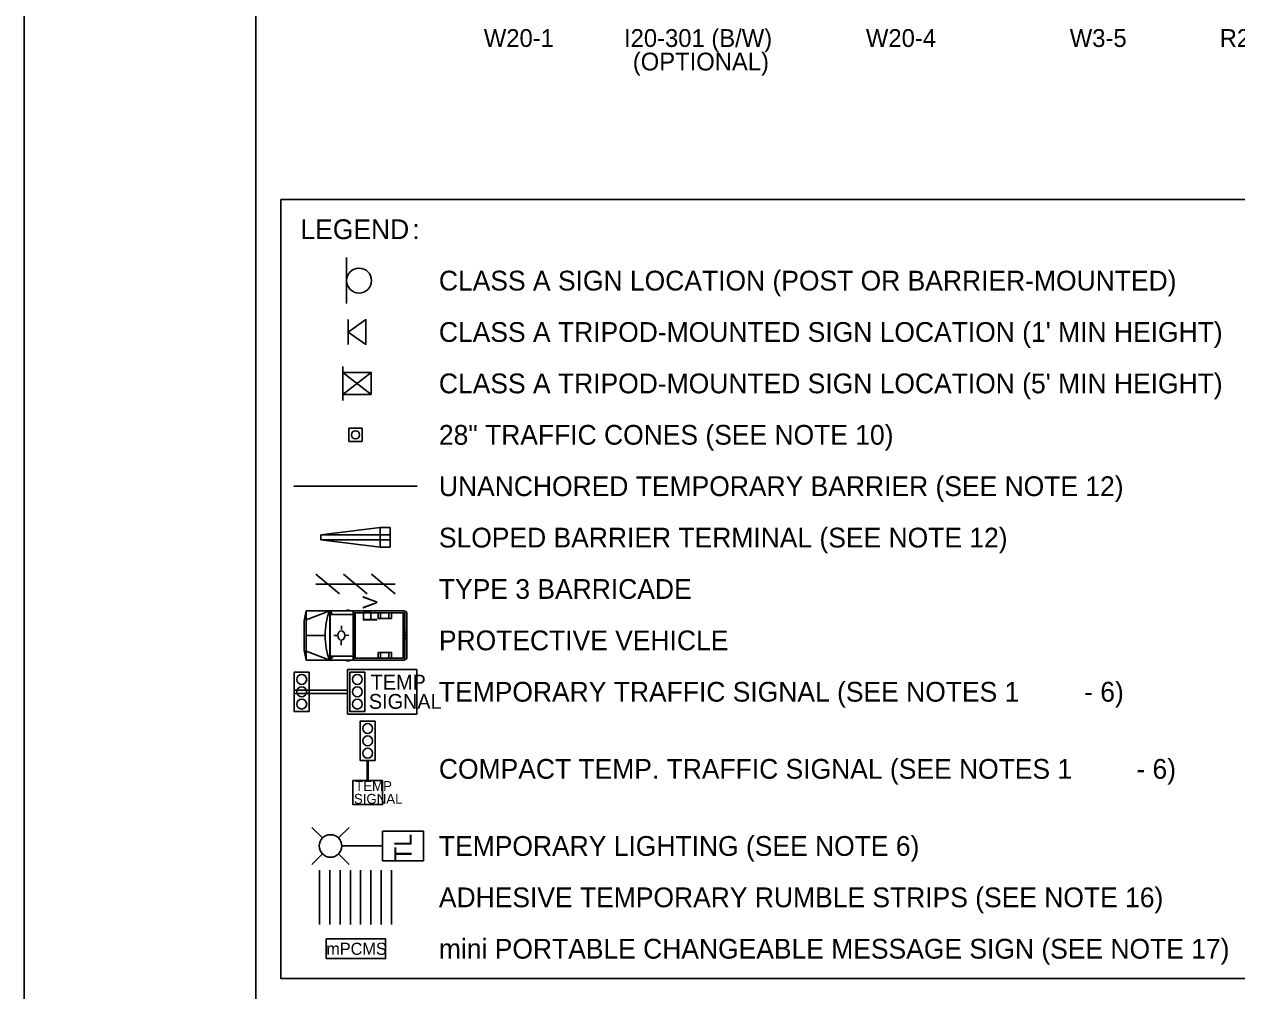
# Model space of a CAD drawing. Extents: x 99977 to 100176, y 99905 to 100011.
# Drawn here: x 99999.062 to 100003.968, y 99911.176 to 99915.088 of the extents above; entities that cross this region are included whole.
import ezdxf

# ---------------------------------------------------------------- set-up
doc = ezdxf.new("R2010")
doc.units = 0
for name, color, linetype in [('SH_GI_PlotLimits', 7, 'Continuous'), ('SH_GI_SheetBorder', 7, 'Continuous'), ('TR_SN_ConstructionSigns', 7, 'Continuous'), ('TR_WZ_BarricadeType3', 7, 'Continuous'), ('TR_WZ_BarrierTemp', 7, 'Continuous'), ('TR_WZ_PortableChangeMessageSign', 7, 'Continuous'), ('TR_WZ_PortableLightStandard', 7, 'Continuous'), ('TR_WZ_PortableSignMount5ftMinBlk-Wht', 7, 'Continuous'), ('TR_WZ_PortableSignMountBlk-Wht', 7, 'Continuous'), ('TR_WZ_ProtectiveVehicle', 7, 'Continuous'), ('TR_WZ_ScaleTerminalEndSection', 7, 'Continuous'), ('TR_WZ_Sign', 7, 'Continuous'), ('TR_WZ_TempSignal', 7, 'Continuous'), ('TR_WZ_TrafficCone', 7, 'Continuous'), ('TR_WZ_WorkZoneDetails', 7, 'Continuous'), ('TR_WZ_WorkZoneTextCurrent', 7, 'Continuous')]:
    doc.layers.add(name, color=color, linetype=linetype)

msp = doc.modelspace()

# ---------------------------------------------------------------- linework, layer by layer
at = {"layer": 'SH_GI_PlotLimits'}
msp.add_lwpolyline([(99999.0625, 99909.6875), (100016.0625, 99909.6875), (100016.0625, 99920.6875), (99999.0625, 99920.6875)], close=True, dxfattribs=at)
at = {"layer": 'SH_GI_SheetBorder'}
msp.add_line((100000, 99920.375), (100000, 99910), dxfattribs=at)
at = {"layer": 'TR_WZ_BarricadeType3'}
for p, q in [((100000.3381, 99912.7823), (100000.2425, 99912.8615)), ((100000.4503, 99912.7823), (100000.3547, 99912.8615)), ((100000.5625, 99912.7823), (100000.4669, 99912.8615)), ((100000.2425, 99912.8219), (100000.5625, 99912.8219))]:
    msp.add_line(p, q, dxfattribs=at)
at = {"layer": 'TR_WZ_BarrierTemp'}
msp.add_line((100000.1525, 99913.2179), (100000.6525, 99913.2179), dxfattribs=at)
at = {"layer": 'TR_WZ_PortableChangeMessageSign'}
msp.add_lwpolyline([(100000.2841, 99911.3059), (100000.5241, 99911.3059), (100000.5241, 99911.3859), (100000.2841, 99911.3859)], close=True, dxfattribs=at)
msp.add_lwpolyline([(100000.2841, 99911.3059), (100000.5241, 99911.3059), (100000.5241, 99911.3859), (100000.2841, 99911.3859), (100000.2841, 99911.3059)], dxfattribs=at)
at = {"layer": 'TR_WZ_PortableLightStandard'}
for p, q in [((100000.2692, 99911.7943), (100000.2261, 99911.8373)), ((100000.3339, 99911.7943), (100000.377, 99911.8373)), ((100000.6777, 99911.8219), (100000.5117, 99911.8219)), ((100000.5117, 99911.8219), (100000.5117, 99911.7019)), ((100000.6777, 99911.8219), (100000.5117, 99911.8219)), ((100000.6777, 99911.8219), (100000.6777, 99911.7019)), ((100000.5117, 99911.7619), (100000.3473, 99911.7619)), ((100000.2692, 99911.7295), (100000.2261, 99911.6864)), ((100000.3339, 99911.7295), (100000.377, 99911.6864)), ((100000.6777, 99911.7019), (100000.5117, 99911.7019)), ((100000.5117, 99911.7019), (100000.6777, 99911.7019))]:
    msp.add_line(p, q, dxfattribs=at)
for points in [[(100000.5117, 99911.8219), (100000.5117, 99911.7619), (100000.5117, 99911.7019)], [(100000.6777, 99911.7019), (100000.6777, 99911.7619), (100000.6777, 99911.8219)]]:
    msp.add_lwpolyline(points, dxfattribs=at)
msp.add_circle((100000.3015, 99911.7619), 0.0457, dxfattribs=at)
msp.add_circle((100000.3015, 99911.7619), 0.0457, dxfattribs=at)
at = {"layer": 'TR_WZ_PortableSignMount5ftMinBlk-Wht'}
for p, q in [((100000.3512, 99913.7029), (100000.3512, 99913.5649)), ((100000.4663, 99913.5891), (100000.3512, 99913.6787)), ((100000.4663, 99913.6787), (100000.3512, 99913.5891)), ((100000.4088, 99913.6339), (100000.4088, 99913.6339)), ((100000.4089, 99913.6338), (100000.4089, 99913.6338))]:
    msp.add_line(p, q, dxfattribs=at)
msp.add_lwpolyline([(100000.4663, 99913.5891), (100000.4663, 99913.6787), (100000.3512, 99913.6787), (100000.3512, 99913.5891)], close=True, dxfattribs=at)
at = {"layer": 'TR_WZ_PortableSignMountBlk-Wht'}
msp.add_line((100000.3728, 99913.7919), (100000.3728, 99913.8919), dxfattribs=at)
msp.add_lwpolyline([(100000.3728, 99913.8418), (100000.4447, 99913.8919), (100000.4447, 99913.7919)], close=True, dxfattribs=at)
at = {"layer": 'TR_WZ_ProtectiveVehicle'}
for p, q in [((100000.2036, 99912.7139), (100000.1944, 99912.6735)), ((100000.2036, 99912.5139), (100000.2036, 99912.7139)), ((100000.2036, 99912.7139), (100000.3925, 99912.7139)), ((100000.2036, 99912.6773), (100000.2981, 99912.7139)), ((100000.2981, 99912.5139), (100000.2981, 99912.7139)), ((100000.2998, 99912.5139), (100000.2998, 99912.7139)), ((100000.3098, 99912.6984), (100000.2998, 99912.7139)), ((100000.2998, 99912.6984), (100000.3925, 99912.6984)), ((100000.3668, 99912.7167), (100000.3781, 99912.7167)), ((100000.3925, 99912.5139), (100000.3925, 99912.7139)), ((100000.601, 99912.7139), (100000.3953, 99912.7139)), ((100000.3953, 99912.5139), (100000.3953, 99912.7139)), ((100000.5952, 99912.7059), (100000.4011, 99912.7059)), ((100000.4011, 99912.5219), (100000.4011, 99912.7059)), ((100000.4938, 99912.7059), (100000.4938, 99912.6829)), ((100000.5038, 99912.7059), (100000.5038, 99912.6829)), ((100000.5378, 99912.7059), (100000.5378, 99912.6829)), ((100000.5488, 99912.7059), (100000.5488, 99912.6829)), ((100000.5952, 99912.5219), (100000.5952, 99912.7059)), ((100000.601, 99912.5139), (100000.601, 99912.7139)), ((100000.6061, 99912.7106), (100000.6017, 99912.7106)), ((100000.6017, 99912.5172), (100000.6017, 99912.7106)), ((100000.6106, 99912.5233), (100000.6106, 99912.7045)), ((100000.1944, 99912.5543), (100000.1944, 99912.6735)), ((100000.3458, 99912.6524), (100000.3455, 99912.6373)), ((100000.5488, 99912.6829), (100000.4938, 99912.6829)), ((100000.2036, 99912.6139), (100000.2795, 99912.6139)), ((100000.315, 99912.6138), (100000.3276, 99912.6138)), ((100000.3451, 99912.5743), (100000.3451, 99912.5904)), ((100000.3592, 99912.6142), (100000.3592, 99912.6142)), ((100000.376, 99912.6147), (100000.3611, 99912.6143)), ((100000.6106, 99912.628), (100000.6017, 99912.6242)), ((100000.6106, 99912.5998), (100000.6017, 99912.6036)), ((100000.6082, 99912.6139), (100000.6041, 99912.6139)), ((100000.6061, 99912.6111), (100000.6061, 99912.6167)), ((100000.2036, 99912.5139), (100000.1944, 99912.5543)), ((100000.2036, 99912.5505), (100000.2981, 99912.5139)), ((100000.5488, 99912.5449), (100000.4938, 99912.5449)), ((100000.4938, 99912.5219), (100000.4938, 99912.5449)), ((100000.5038, 99912.5219), (100000.5038, 99912.5449)), ((100000.5378, 99912.5219), (100000.5378, 99912.5449)), ((100000.5488, 99912.5219), (100000.5488, 99912.5449)), ((100000.2036, 99912.5139), (100000.3925, 99912.5139)), ((100000.2998, 99912.5139), (100000.3118, 99912.5294)), ((100000.2998, 99912.5294), (100000.3925, 99912.5294)), ((100000.3668, 99912.5111), (100000.3781, 99912.5111)), ((100000.601, 99912.5139), (100000.3953, 99912.5139)), ((100000.5952, 99912.5219), (100000.4011, 99912.5219)), ((100000.6061, 99912.5172), (100000.6017, 99912.5172))]:
    msp.add_line(p, q, dxfattribs=at)
for centre, major_axis, start_param, end_param in [((100000.4331, 99912.6139), (0, -0.2099), 4.215852, 5.209111), ((100000.6061, 99912.7045), (0, 0.0061), 4.712389, 6.283185), ((100000.6061, 99912.5233), (0, -0.0061), 6.283185, 7.853982)]:
    msp.add_ellipse(centre, major_axis=major_axis, ratio=0.73155, start_param=start_param, end_param=end_param, dxfattribs=at)
for centre, major_axis in [((100000.3451, 99912.6139), (0, 0.0193)), ((100000.6061, 99912.6139), (0, 0.00282))]:
    msp.add_ellipse(centre, major_axis=major_axis, ratio=0.73155, dxfattribs=at)
at = {"layer": 'TR_WZ_ScaleTerminalEndSection'}
for p, q in [((100000.5025, 99913.051), (100000.2625, 99913.021)), ((100000.5025, 99913.051), (100000.5025, 99912.971)), ((100000.5425, 99913.051), (100000.5025, 99913.051)), ((100000.5425, 99913.051), (100000.5425, 99912.971)), ((100000.2625, 99913.021), (100000.5425, 99913.021)), ((100000.2625, 99913.021), (100000.2625, 99913.001)), ((100000.2625, 99913.001), (100000.5425, 99913.001)), ((100000.5025, 99912.971), (100000.2625, 99913.001)), ((100000.5425, 99912.971), (100000.5025, 99912.971))]:
    msp.add_line(p, q, dxfattribs=at)
at = {"layer": 'TR_WZ_Sign'}
msp.add_line((100000.3668, 99913.9567), (100000.3668, 99914.1431), dxfattribs=at)
msp.add_circle((100000.4172, 99914.05), 0.0504, dxfattribs=at)
msp.add_circle((100000.4172, 99914.05), 0.0504, dxfattribs=at)
at = {"layer": 'TR_WZ_TempSignal'}
for p, q in [((100000.215, 99912.4658), (100000.1551, 99912.4658)), ((100000.1551, 99912.4658), (100000.1551, 99912.306)), ((100000.215, 99912.306), (100000.215, 99912.4658)), ((100000.3701, 99912.4759), (100000.6501, 99912.4759)), ((100000.3701, 99912.2959), (100000.3701, 99912.4759)), ((100000.6501, 99912.4759), (100000.3701, 99912.4759)), ((100000.3701, 99912.4759), (100000.3701, 99912.3926)), ((100000.44, 99912.4658), (100000.3801, 99912.4658)), ((100000.3801, 99912.4658), (100000.3801, 99912.306)), ((100000.44, 99912.306), (100000.44, 99912.4658)), ((100000.6501, 99912.4759), (100000.6501, 99912.2959)), ((100000.6501, 99912.2959), (100000.6501, 99912.4759)), ((100000.3701, 99912.3926), (100000.1551, 99912.3926)), ((100000.1551, 99912.3926), (100000.1551, 99912.3792)), ((100000.3701, 99912.3792), (100000.3701, 99912.3926)), ((100000.3701, 99912.3926), (100000.3701, 99912.3792)), ((100000.1551, 99912.3792), (100000.3701, 99912.3792)), ((100000.3701, 99912.3792), (100000.3701, 99912.2959)), ((100000.1551, 99912.306), (100000.215, 99912.306)), ((100000.6501, 99912.2959), (100000.3701, 99912.2959)), ((100000.3701, 99912.2959), (100000.6501, 99912.2959)), ((100000.3801, 99912.306), (100000.44, 99912.306)), ((100000.4819, 99912.2672), (100000.422, 99912.2672)), ((100000.422, 99912.2672), (100000.422, 99912.1075)), ((100000.4819, 99912.1075), (100000.4819, 99912.2672)), ((100000.422, 99912.1075), (100000.4819, 99912.1075)), ((100000.5119, 99912.0275), (100000.3919, 99912.0275)), ((100000.3919, 99912.0275), (100000.3919, 99911.983)), ((100000.5119, 99911.9297), (100000.5119, 99912.0275)), ((100000.3919, 99911.983), (100000.3919, 99911.9742)), ((100000.3919, 99911.9742), (100000.3919, 99911.9297)), ((100000.3919, 99911.9297), (100000.5119, 99911.9297))]:
    msp.add_line(p, q, dxfattribs=at)
for points in [[(100000.215, 99912.4658), (100000.1551, 99912.4658), (100000.1551, 99912.306), (100000.215, 99912.306), (100000.215, 99912.4658)], [(100000.44, 99912.4658), (100000.3801, 99912.4658), (100000.3801, 99912.306), (100000.44, 99912.306), (100000.44, 99912.4658)], [(100000.4819, 99912.2672), (100000.422, 99912.2672), (100000.422, 99912.1075), (100000.4819, 99912.1075), (100000.4819, 99912.2672)], [(100000.5119, 99912.0275), (100000.3919, 99912.0275), (100000.3919, 99911.9297), (100000.5119, 99911.9297), (100000.5119, 99912.0275)]]:
    msp.add_lwpolyline(points, dxfattribs=at)
msp.add_lwpolyline([(100000.4494, 99912.1075), (100000.4544, 99912.1075), (100000.4544, 99912.0275), (100000.4494, 99912.0275)], close=True, dxfattribs=at)
for centre in [(100000.1851, 99912.4358), (100000.1851, 99912.4358), (100000.4101, 99912.4358), (100000.4101, 99912.4358), (100000.1851, 99912.3859), (100000.1851, 99912.3859), (100000.4101, 99912.3859), (100000.4101, 99912.3859), (100000.1851, 99912.336), (100000.1851, 99912.336), (100000.4101, 99912.336), (100000.4101, 99912.336), (100000.4519, 99912.2373), (100000.4519, 99912.2373), (100000.4519, 99912.1874), (100000.4519, 99912.1874), (100000.4519, 99912.1374), (100000.4519, 99912.1374)]:
    msp.add_circle(centre, 0.02, dxfattribs=at)
at = {"layer": 'TR_WZ_TrafficCone'}
for points in [[(100000.3759, 99913.4526), (100000.4293, 99913.4526), (100000.4293, 99913.3992), (100000.3759, 99913.3992), (100000.3759, 99913.4526)], [(100000.3759, 99913.3992), (100000.4293, 99913.3992), (100000.4293, 99913.4526), (100000.3759, 99913.4526), (100000.3759, 99913.3992)]]:
    msp.add_lwpolyline(points, dxfattribs=at)
msp.add_circle((100000.4026, 99913.4259), 0.0167, dxfattribs=at)
at = {"layer": 'TR_WZ_WorkZoneDetails'}
for p, q in [((100000.2574, 99911.4439), (100000.2574, 99911.6639)), ((100000.2991, 99911.4439), (100000.2991, 99911.6639)), ((100000.3403, 99911.4439), (100000.3403, 99911.6639)), ((100000.382, 99911.4439), (100000.382, 99911.6639)), ((100000.4232, 99911.4439), (100000.4232, 99911.6639)), ((100000.4649, 99911.4439), (100000.4649, 99911.6639)), ((100000.5061, 99911.4439), (100000.5061, 99911.6639)), ((100000.5478, 99911.4439), (100000.5478, 99911.6639))]:
    msp.add_line(p, q, dxfattribs=at)
msp.add_lwpolyline([(100000.4447, 99913.7919), (100000.4447, 99913.8919), (100000.3728, 99913.8418), (100000.4447, 99913.7919)], dxfattribs=at)
at = {"layer": 'TR_WZ_WorkZoneTextCurrent'}
msp.add_lwpolyline([(100000.1, 99914.3779), (100004.1384, 99914.3779), (100004.1384, 99911.2259), (100000.1, 99911.2259)], close=True, dxfattribs=at)

# ---------------------------------------------------------------- texts
at = {"layer": 'TR_SN_ConstructionSigns'}
for s, p in [('W20-1', (100000.9217, 99914.9956)), ('I20-301 (B/W)', (100001.4889, 99914.9956)), ('W20-4', (100002.4676, 99914.9956)), ('W3-5', (100003.2922, 99914.9956)), ('R2-1 (B/W)', (100003.8988, 99914.9956)), ('(OPTIONAL)', (100001.5244, 99914.9005))]:
    msp.add_text(s, height=0.072, rotation=360, dxfattribs=at).set_placement(p)
at = {"layer": 'TR_WZ_PortableChangeMessageSign'}
msp.add_text('mPCMS', height=0.04909, rotation=360, dxfattribs=at).set_placement((100000.2845, 99911.3214))
at = {"layer": 'TR_WZ_PortableLightStandard'}
msp.add_text('TL', height=0.07, rotation=90, dxfattribs=at).set_placement((100000.6297, 99911.7017))
at = {"layer": 'TR_WZ_ProtectiveVehicle'}
msp.add_text('PV', height=0.06, rotation=90, dxfattribs=at).set_placement((100000.4913, 99912.6677))
at = {"layer": 'TR_WZ_TempSignal'}
for s, height, p in [('TEMP', 0.06, (100000.4641, 99912.3949)), ('SIGNAL', 0.06, (100000.4567, 99912.3169)), ('TEMP', 0.04, (100000.4013, 99911.9846)), ('SIGNAL', 0.04, (100000.3963, 99911.9326))]:
    msp.add_text(s, height=height, dxfattribs=at).set_placement(p)
at = {"layer": 'TR_WZ_WorkZoneTextCurrent'}
for s, p in [('LEGEND', (100000.18, 99914.2179)), (':', (100000.6328, 99914.2179)), ('CLASS A SIGN LOCATION (POST OR BARRIER-MOUNTED)', (100000.74, 99914.0099)), ("CLASS A TRIPOD-MOUNTED SIGN LOCATION (1' MIN HEIGHT)", (100000.74, 99913.8019)), ("CLASS A TRIPOD-MOUNTED SIGN LOCATION (5' MIN HEIGHT)", (100000.74, 99913.5939)), ('28" TRAFFIC CONES (SEE NOTE 10)', (100000.74, 99913.3859)), ('UNANCHORED TEMPORARY BARRIER (SEE NOTE 12)', (100000.74, 99913.1779)), ('SLOPED BARRIER TERMINAL (SEE NOTE 12)', (100000.74, 99912.9699)), ('TYPE 3 BARRICADE', (100000.74, 99912.7619)), ('PROTECTIVE VEHICLE', (100000.74, 99912.5539)), ('TEMPORARY TRAFFIC SIGNAL (SEE NOTES 1', (100000.74, 99912.3459)), ('- 6)', (100003.3504, 99912.3459)), ('COMPACT TEMP. TRAFFIC SIGNAL (SEE NOTES 1', (100000.74, 99912.0339)), ('- 6)', (100003.5616, 99912.0339)), ('TEMPORARY LIGHTING (SEE NOTE 6)', (100000.74, 99911.7219)), ('ADHESIVE TEMPORARY RUMBLE STRIPS (SEE NOTE 16)', (100000.74, 99911.5139)), ('mini PORTABLE CHANGEABLE MESSAGE SIGN (SEE NOTE 17)', (100000.74, 99911.3059))]:
    msp.add_text(s, height=0.08, rotation=360, dxfattribs=at).set_placement(p)

doc.saveas('drawing.dxf')
